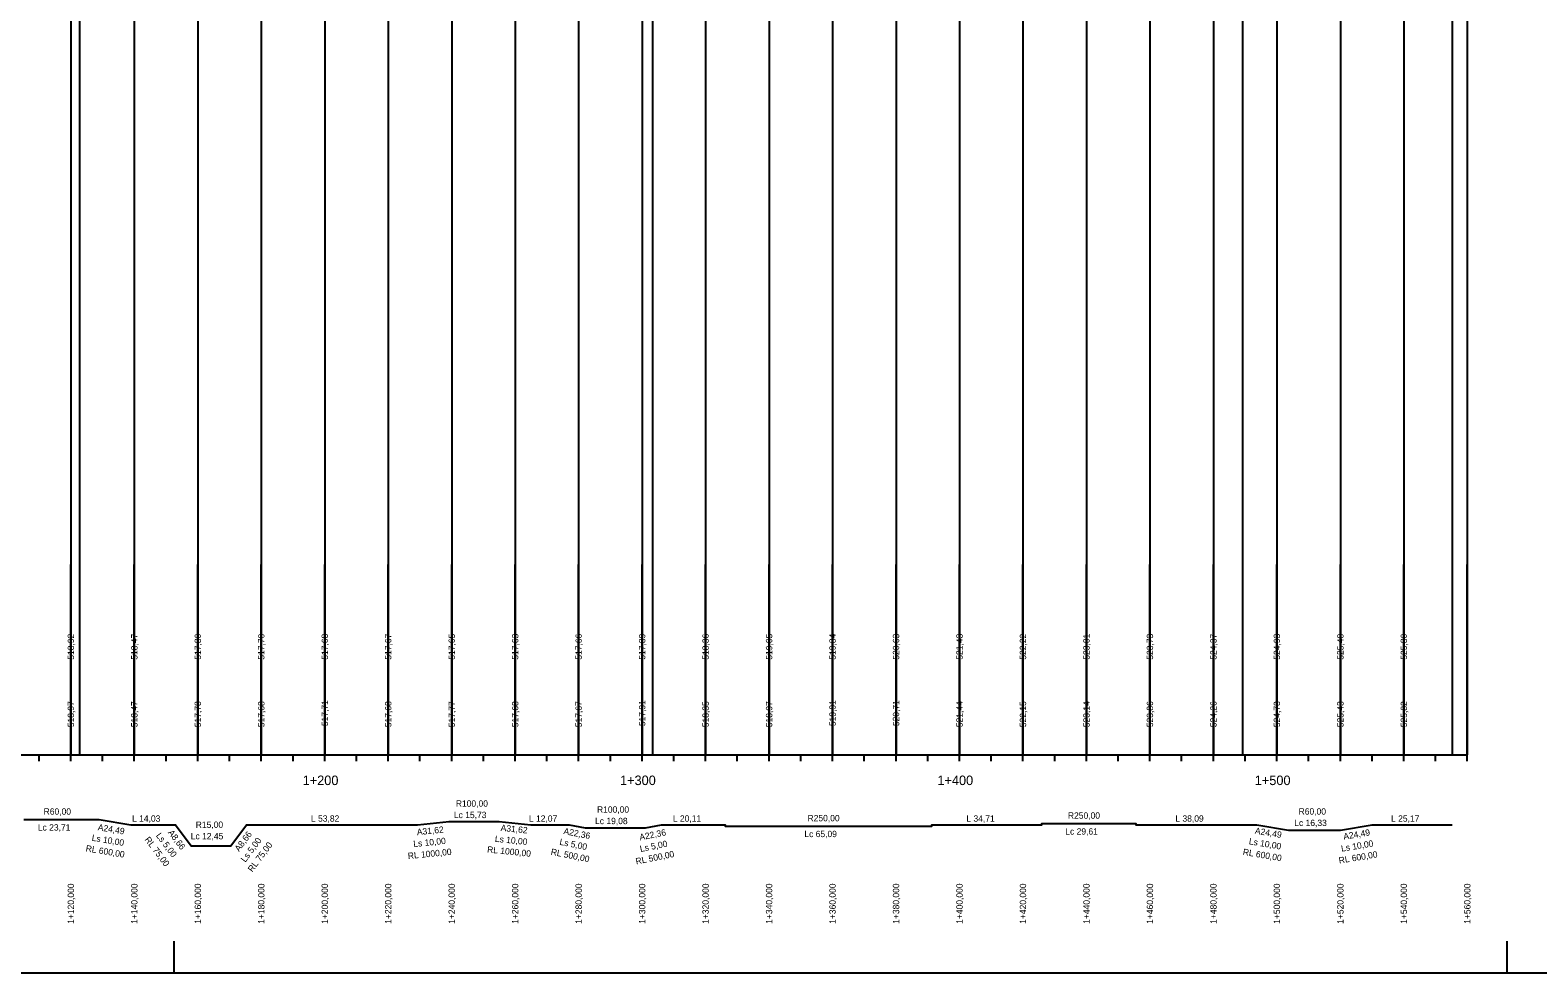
# Model space of a CAD drawing. Extents: x -632716 to -629545, y -1094726 to -1088285.
# Drawn here: x -631412.3 to -630937.2, y -1092797.3 to -1092500.3 of the extents above; entities that cross this region are included whole.
import ezdxf

# ---------------------------------------------------------------- set-up
doc = ezdxf.new("R2010")
doc.units = 0
for name, color, linetype in [('20', 7, 'Continuous'), ('formát', 7, 'Continuous'), ('NIVELETA_VYSKY', 7, 'Continuous'), ('REZ_POPIS', 7, 'Continuous'), ('REZ_TABULKA', 7, 'Continuous'), ('REZ_TENKA', 7, 'Continuous'), ('REZ_TLUSTA', 7, 'Continuous'), ('SKLONY_NIVELETA', 7, 'Continuous'), ('TEREN_VYSKY', 7, 'Continuous')]:
    doc.layers.add(name, color=color, linetype=linetype)

msp = doc.modelspace()

# ---------------------------------------------------------------- linework, layer by layer
at = {"layer": '20'}
for points in [[(-630959.44, -1092278.62), (-630959.44, -1092678.62), (-630959.44, -1092728.62), (-630959.44, -1092668.62)], [(-630979.44, -1092320.63), (-630979.44, -1092678.62), (-630979.44, -1092728.62), (-630979.44, -1092668.62)], [(-630999.44, -1092324.59), (-630999.44, -1092678.62), (-630999.44, -1092728.62), (-630999.44, -1092668.62)], [(-631019.44, -1092329.36), (-631019.44, -1092678.62), (-631019.44, -1092728.62), (-631019.44, -1092668.62)], [(-631039.44, -1092334.94), (-631039.44, -1092678.62), (-631039.44, -1092728.62), (-631039.44, -1092668.62)], [(-631059.44, -1092341.34), (-631059.44, -1092678.62), (-631059.44, -1092728.62), (-631059.44, -1092668.62)], [(-631079.44, -1092348.55), (-631079.44, -1092678.62), (-631079.44, -1092728.62), (-631079.44, -1092668.62)], [(-631099.44, -1092356.42), (-631099.44, -1092678.62), (-631099.44, -1092728.62), (-631099.44, -1092668.62)], [(-631119.44, -1092364.35), (-631119.44, -1092678.62), (-631119.44, -1092728.62), (-631119.44, -1092668.62)], [(-631139.44, -1092372.28), (-631139.44, -1092678.62), (-631139.44, -1092728.62), (-631139.44, -1092668.62)], [(-631159.44, -1092380.21), (-631159.44, -1092678.62), (-631159.44, -1092728.62), (-631159.44, -1092668.62)], [(-631399.44, -1092389.4), (-631399.44, -1092678.62), (-631399.44, -1092728.62), (-631399.44, -1092668.62)], [(-631179.44, -1092388.14), (-631179.44, -1092678.62), (-631179.44, -1092728.62), (-631179.44, -1092668.62)], [(-631379.44, -1092393.88), (-631379.44, -1092678.62), (-631379.44, -1092728.62), (-631379.44, -1092668.62)], [(-631219.44, -1092399.67), (-631219.44, -1092678.62), (-631219.44, -1092728.62), (-631219.44, -1092668.62)], [(-631199.44, -1092395.04), (-631199.44, -1092678.62), (-631199.44, -1092728.62), (-631199.44, -1092668.62)], [(-631359.44, -1092400.64), (-631359.44, -1092678.62), (-631359.44, -1092728.62), (-631359.44, -1092668.62)], [(-631339.44, -1092401.6), (-631339.44, -1092678.62), (-631339.44, -1092728.62), (-631339.44, -1092668.62)], [(-631319.44, -1092401.78), (-631319.44, -1092678.62), (-631319.44, -1092728.62), (-631319.44, -1092668.62)], [(-631299.44, -1092401.96), (-631299.44, -1092678.62), (-631299.44, -1092728.62), (-631299.44, -1092668.62)], [(-631279.44, -1092402.14), (-631279.44, -1092678.62), (-631279.44, -1092728.62), (-631279.44, -1092668.62)], [(-631259.44, -1092402.32), (-631259.44, -1092678.62), (-631259.44, -1092728.62), (-631259.44, -1092668.62)], [(-631239.44, -1092402.05), (-631239.44, -1092678.62), (-631239.44, -1092728.62), (-631239.44, -1092668.62)]]:
    msp.add_lwpolyline(points, dxfattribs=at)
at = {"layer": 'formát'}
for p, q in [((-631366.91, -1092797.28), (-631366.91, -1092787.28)), ((-630946.91, -1092797.28), (-630946.91, -1092787.28))]:
    msp.add_line(p, q, dxfattribs=at)
msp.add_lwpolyline([(-632626.91, -1092797.28), (-630526.91, -1092797.28), (-630526.91, -1092203.28), (-632626.91, -1092203.28)], close=True, dxfattribs=at)
at = {"layer": 'REZ_TABULKA'}
msp.add_lwpolyline([(-631414.24, -1092748.95), (-631390.53, -1092748.95), (-631390.53, -1092748.95), (-631380.53, -1092750.62), (-631380.53, -1092750.62), (-631366.5, -1092750.62), (-631366.5, -1092750.62), (-631361.5, -1092757.28), (-631361.5, -1092757.28), (-631349.05, -1092757.28), (-631349.05, -1092757.28), (-631344.05, -1092750.62), (-631344.05, -1092750.62), (-631290.23, -1092750.62), (-631290.23, -1092750.62), (-631280.23, -1092749.62), (-631280.23, -1092749.62), (-631264.5, -1092749.62), (-631264.5, -1092749.62), (-631254.5, -1092750.62), (-631254.5, -1092750.62), (-631242.43, -1092750.62), (-631242.43, -1092750.62), (-631237.43, -1092751.62), (-631237.43, -1092751.62), (-631218.35, -1092751.62), (-631218.35, -1092751.62), (-631213.35, -1092750.62), (-631213.35, -1092750.62), (-631193.24, -1092750.62), (-631193.24, -1092751.02), (-631128.16, -1092751.02), (-631128.16, -1092750.62), (-631093.45, -1092750.62), (-631093.45, -1092750.22), (-631063.84, -1092750.22), (-631063.84, -1092750.62), (-631025.75, -1092750.62), (-631025.75, -1092750.62), (-631015.75, -1092752.28), (-631015.75, -1092752.28), (-630999.42, -1092752.28), (-630999.42, -1092752.28), (-630989.42, -1092750.62), (-630989.42, -1092750.62), (-630964.25, -1092750.62)], dxfattribs=at)
at = {"layer": 'REZ_TENKA'}
for p, q in [((-631409.44, -1092730.62), (-631409.44, -1092728.62)), ((-631399.44, -1092730.62), (-631399.44, -1092728.62)), ((-631389.44, -1092730.62), (-631389.44, -1092728.62)), ((-631379.44, -1092730.62), (-631379.44, -1092728.62)), ((-631369.44, -1092730.62), (-631369.44, -1092728.62)), ((-631359.44, -1092730.62), (-631359.44, -1092728.62)), ((-631349.44, -1092730.62), (-631349.44, -1092728.62)), ((-631339.44, -1092730.62), (-631339.44, -1092728.62)), ((-631329.44, -1092730.62), (-631329.44, -1092728.62)), ((-631309.44, -1092730.62), (-631309.44, -1092728.62)), ((-631299.44, -1092730.62), (-631299.44, -1092728.62)), ((-631289.44, -1092730.62), (-631289.44, -1092728.62)), ((-631279.44, -1092730.62), (-631279.44, -1092728.62)), ((-631269.44, -1092730.62), (-631269.44, -1092728.62)), ((-631259.44, -1092730.62), (-631259.44, -1092728.62)), ((-631249.44, -1092730.62), (-631249.44, -1092728.62)), ((-631239.44, -1092730.62), (-631239.44, -1092728.62)), ((-631229.44, -1092730.62), (-631229.44, -1092728.62)), ((-631209.44, -1092730.62), (-631209.44, -1092728.62)), ((-631199.44, -1092730.62), (-631199.44, -1092728.62)), ((-631189.44, -1092730.62), (-631189.44, -1092728.62)), ((-631179.44, -1092730.62), (-631179.44, -1092728.62)), ((-631169.44, -1092730.62), (-631169.44, -1092728.62)), ((-631159.44, -1092730.62), (-631159.44, -1092728.62)), ((-631149.44, -1092730.62), (-631149.44, -1092728.62)), ((-631139.44, -1092730.62), (-631139.44, -1092728.62)), ((-631129.44, -1092730.62), (-631129.44, -1092728.62)), ((-631109.44, -1092730.62), (-631109.44, -1092728.62)), ((-631099.44, -1092730.62), (-631099.44, -1092728.62)), ((-631089.44, -1092730.62), (-631089.44, -1092728.62)), ((-631079.44, -1092730.62), (-631079.44, -1092728.62)), ((-631069.44, -1092730.62), (-631069.44, -1092728.62)), ((-631059.44, -1092730.62), (-631059.44, -1092728.62)), ((-631049.44, -1092730.62), (-631049.44, -1092728.62)), ((-631039.44, -1092730.62), (-631039.44, -1092728.62)), ((-631029.44, -1092730.62), (-631029.44, -1092728.62)), ((-631009.44, -1092730.62), (-631009.44, -1092728.62)), ((-630999.44, -1092730.62), (-630999.44, -1092728.62)), ((-630989.44, -1092730.62), (-630989.44, -1092728.62)), ((-630979.44, -1092730.62), (-630979.44, -1092728.62)), ((-630969.44, -1092730.62), (-630969.44, -1092728.62)), ((-630959.44, -1092730.62), (-630959.44, -1092728.62))]:
    msp.add_line(p, q, dxfattribs=at)
at = {"layer": 'REZ_TLUSTA'}
for p, q in [((-631319.44, -1092730.62), (-631319.44, -1092726.62)), ((-631219.44, -1092730.62), (-631219.44, -1092726.62)), ((-631119.44, -1092730.62), (-631119.44, -1092726.62)), ((-631019.44, -1092730.62), (-631019.44, -1092726.62)), ((-632519.44, -1092728.62), (-630959.44, -1092728.62))]:
    msp.add_line(p, q, dxfattribs=at)
at = {"layer": 'SKLONY_NIVELETA'}
for p, q in [((-630964.25, -1092218.09), (-630964.25, -1092728.62)), ((-631030.23, -1092228.97), (-631030.23, -1092728.62)), ((-631396.67, -1092287.33), (-631396.67, -1092728.62)), ((-631359.38, -1092301.42), (-631359.38, -1092728.62)), ((-631216.2, -1092302.72), (-631216.2, -1092728.62))]:
    msp.add_line(p, q, dxfattribs=at)

# ---------------------------------------------------------------- texts
at = {"layer": 'NIVELETA_VYSKY'}
for s, p in [('518,92', (-631398.44, -1092698.62)), ('518,47', (-631378.44, -1092698.62)), ('517,80', (-631358.44, -1092698.62)), ('517,70', (-631338.44, -1092698.62)), ('517,68', (-631318.44, -1092698.62)), ('517,67', (-631298.44, -1092698.62)), ('517,65', (-631278.44, -1092698.62)), ('517,63', (-631258.44, -1092698.62)), ('517,66', (-631238.44, -1092698.62)), ('517,89', (-631218.44, -1092698.62)), ('518,36', (-631198.44, -1092698.62)), ('519,05', (-631178.44, -1092698.62)), ('519,84', (-631158.44, -1092698.62)), ('520,63', (-631138.44, -1092698.62)), ('521,43', (-631118.44, -1092698.62)), ('522,22', (-631098.44, -1092698.62)), ('523,01', (-631078.44, -1092698.62)), ('523,73', (-631058.44, -1092698.62)), ('524,37', (-631038.44, -1092698.62)), ('524,93', (-631018.44, -1092698.62)), ('525,40', (-630998.44, -1092698.62)), ('525,80', (-630978.44, -1092698.62))]:
    msp.add_text(s, height=2, rotation=90, dxfattribs=at).set_placement(p)
at = {"layer": 'REZ_POPIS'}
for s, p in [('1+200', (-631326.4, -1092738.12)), ('1+300', (-631226.4, -1092738.12)), ('1+400', (-631126.4, -1092738.12)), ('1+500', (-631026.4, -1092738.12))]:
    msp.add_text(s, height=3, dxfattribs=at).set_placement(p)
at = {"layer": 'REZ_TABULKA'}
for s, p in [('R60,00', (-631408.01, -1092747.45)), ('R100,00', (-631278.13, -1092744.93)), ('R100,00', (-631233.65, -1092746.83)), ('R60,00', (-631012.58, -1092747.42)), ('Lc 23,71', (-631409.84, -1092752.45)), ('L 14,03', (-631380.15, -1092749.66)), ('R15,00', (-631360.09, -1092751.6)), ('L 53,82', (-631323.77, -1092749.66)), ('Lc 15,73', (-631278.75, -1092748.53)), ('L 12,07', (-631255.1, -1092749.66)), ('Lc 19,08', (-631234.27, -1092750.43)), ('L 20,11', (-631209.76, -1092749.66)), ('R250,00', (-631167.32, -1092749.52)), ('L 34,71', (-631117.27, -1092749.66)), ('R250,00', (-631085.27, -1092748.72)), ('L 38,09', (-631051.42, -1092749.66)), ('Lc 16,33', (-631013.96, -1092751.02)), ('L 25,17', (-630983.46, -1092749.66)), ('Lc 12,45', (-631361.66, -1092755.2)), ('Lc 65,09', (-631168.32, -1092754.52)), ('Lc 29,61', (-631086.1, -1092753.72))]:
    msp.add_text(s, height=2, dxfattribs=at).set_placement(p)
for s, rotation, p in [('A24,49', 350.5377, (-631391.05, -1092752.31)), ('A31,62', 5.7106, (-631290.32, -1092753.93)), ('A31,62', 354.2894, (-631264.07, -1092752.54)), ('Ls 10,00', 350.5377, (-631392.96, -1092755.64)), ('RL 75,00', 306.8699, (-631376.3, -1092755.31)), ('Ls 5,00', 306.8699, (-631372.73, -1092754.07)), ('A8,66', 306.8699, (-631368.94, -1092753.13)), ('A8,66', 53.1301, (-631346.44, -1092759.23)), ('Ls 5,00', 53.1301, (-631344.48, -1092762.61)), ('Ls 10,00', 5.7106, (-631291.43, -1092757.66)), ('Ls 10,00', 354.2894, (-631265.9, -1092755.98)), ('Ls 5,00', 348.6901, (-631245.59, -1092756.91)), ('A22,36', 348.6901, (-631244.32, -1092753.5)), ('Ls 5,00', 11.3099, (-631219.93, -1092759.22)), ('A22,36', 11.3099, (-631220.08, -1092755.58)), ('Ls 10,00', 350.5377, (-631028.37, -1092756.75)), ('A24,49', 350.5377, (-631026.46, -1092753.42)), ('Ls 10,00', 9.4623, (-630999.04, -1092759.11)), ('A24,49', 9.4623, (-630998.32, -1092755.34)), ('RL 600,00', 350.5377, (-631394.86, -1092758.98)), ('RL 75,00', 53.1301, (-631342.28, -1092765.69)), ('RL 1000,00', 5.7106, (-631293.16, -1092761.45)), ('RL 1000,00', 354.2894, (-631268.34, -1092759.35)), ('RL 500,00', 348.6901, (-631248.35, -1092760.03)), ('RL 500,00', 11.3099, (-631221.28, -1092763.16)), ('RL 600,00', 350.5377, (-631030.28, -1092760.09)), ('RL 600,00', 9.4623, (-630999.77, -1092762.88)), ('1+120,000', 90, (-631398.44, -1092781.83)), ('1+140,000', 90, (-631378.44, -1092781.83)), ('1+160,000', 90, (-631358.44, -1092781.83)), ('1+180,000', 90, (-631338.44, -1092781.83)), ('1+200,000', 90, (-631318.44, -1092781.83)), ('1+220,000', 90, (-631298.44, -1092781.83)), ('1+240,000', 90, (-631278.44, -1092781.83)), ('1+260,000', 90, (-631258.44, -1092781.83)), ('1+280,000', 90, (-631238.44, -1092781.83)), ('1+300,000', 90, (-631218.44, -1092781.83)), ('1+320,000', 90, (-631198.44, -1092781.83)), ('1+340,000', 90, (-631178.44, -1092781.83)), ('1+360,000', 90, (-631158.44, -1092781.83)), ('1+380,000', 90, (-631138.44, -1092781.83)), ('1+400,000', 90, (-631118.44, -1092781.83)), ('1+420,000', 90, (-631098.44, -1092781.83)), ('1+440,000', 90, (-631078.44, -1092781.83)), ('1+460,000', 90, (-631058.44, -1092781.83)), ('1+480,000', 90, (-631038.44, -1092781.83)), ('1+500,000', 90, (-631018.44, -1092781.83)), ('1+520,000', 90, (-630998.44, -1092781.83)), ('1+540,000', 90, (-630978.44, -1092781.83)), ('1+560,000', 90, (-630958.44, -1092781.83))]:
    msp.add_text(s, height=2, rotation=rotation, dxfattribs=at).set_placement(p)
at = {"layer": 'TEREN_VYSKY'}
for s, p in [('518,97', (-631398.44, -1092719.88)), ('518,47', (-631378.44, -1092719.88)), ('517,78', (-631358.44, -1092719.88)), ('517,68', (-631338.44, -1092719.88)), ('517,71', (-631318.44, -1092719.54)), ('517,68', (-631298.44, -1092719.88)), ('517,77', (-631278.44, -1092719.88)), ('517,68', (-631258.44, -1092719.88)), ('517,67', (-631238.44, -1092719.88)), ('517,91', (-631218.44, -1092719.54)), ('518,35', (-631198.44, -1092719.88)), ('518,97', (-631178.44, -1092719.88)), ('519,91', (-631158.44, -1092719.54)), ('520,71', (-631138.44, -1092719.54)), ('521,44', (-631118.44, -1092719.88)), ('522,15', (-631098.44, -1092719.88)), ('523,14', (-631078.44, -1092719.88)), ('523,86', (-631058.44, -1092719.88)), ('524,26', (-631038.44, -1092719.88)), ('524,73', (-631018.44, -1092719.88)), ('525,43', (-630998.44, -1092719.88)), ('525,82', (-630978.44, -1092719.88))]:
    msp.add_text(s, height=2, rotation=90, dxfattribs=at).set_placement(p)

doc.saveas('drawing.dxf')
